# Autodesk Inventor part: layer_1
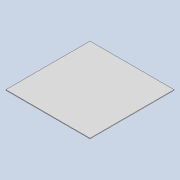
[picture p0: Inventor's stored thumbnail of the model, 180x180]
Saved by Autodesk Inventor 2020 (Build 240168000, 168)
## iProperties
Created: 2021-10
Part Number: layer_1
Material: Generic
Document SubType Name: Modeling
Designer: Shuang Peng
Density: 1 g/cm^3
Appearance: Default
Author: Shuang Peng
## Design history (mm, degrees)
sketch "Sketch1"
  geometry: L1 (0, 0)-(40, 0); L2 (40, 0)-(40, -40); L3 (40, -40)-(0, -40); L4 (0, -40)-(0, 0)
  constraints: 8 end point, 2 parallel, 1 horizontal, 1 perpendicular
  dimensions: "d0" = 40 distance of L2.end L3.end; "d1" = 40 distance of L1.end L2.end
extrude "Extrusion1" new body sketch "Sketch1" distance "d2" = 0.3; taper "d3" = 0 deg
body "Solid1"
